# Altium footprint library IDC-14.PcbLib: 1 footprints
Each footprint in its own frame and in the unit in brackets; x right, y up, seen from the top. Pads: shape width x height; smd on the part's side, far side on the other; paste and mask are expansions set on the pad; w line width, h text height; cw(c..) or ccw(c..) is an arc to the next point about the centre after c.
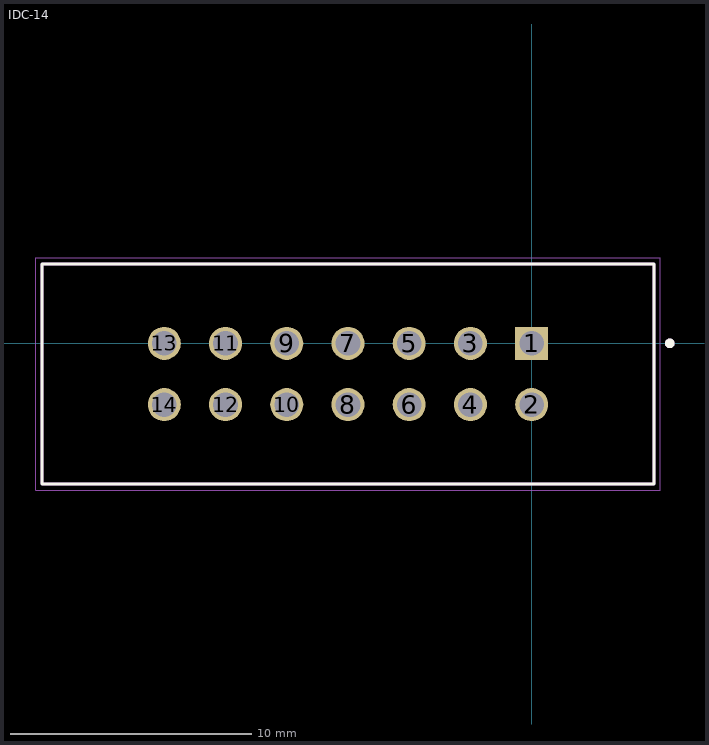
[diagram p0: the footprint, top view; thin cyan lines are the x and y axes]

## IDC-14 [mm]
pads (14):
  rect 1.37x1.37 hole 1.02: 1(0,0)
  round 1.37 hole 1.02: 2(0,-2.54) 3(-2.54,0) 4(-2.54,-2.54) 5(-5.08,0) 6(-5.08,-2.54) 7(-7.62,0) 8(-7.62,-2.54) 9(-10.16,0) 10(-10.16,-2.54) 11(-12.7,0) 12(-12.7,-2.54) 13(-15.24,0) 14(-15.24,-2.54)
Top Overlay:
  circle w0.2: c5.73,0 r0.1
  lines w0.127: -20.32,-5.842 -20.32,3.302 5.08,3.302 5.08,-5.842 -20.32,-5.842
Mechanical 13:
  circle w0.2: c5.73,0 r0.1
  lines w0.127: -20.32,-5.842 -20.32,3.302 5.08,3.302 5.08,-5.842 ; -20.32,-5.842 5.08,-5.842 ; -20.32,-5.842 5.08,-5.842
Mechanical 15:
  lines w0.05: -20.57,-6.092 -20.57,3.552 5.33,3.552 5.33,-6.092 -20.57,-6.092
3D body "IDC-14.STEP": height 9.25, standoff -3.66, extent -20.32,-5.842 5.08,3.302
